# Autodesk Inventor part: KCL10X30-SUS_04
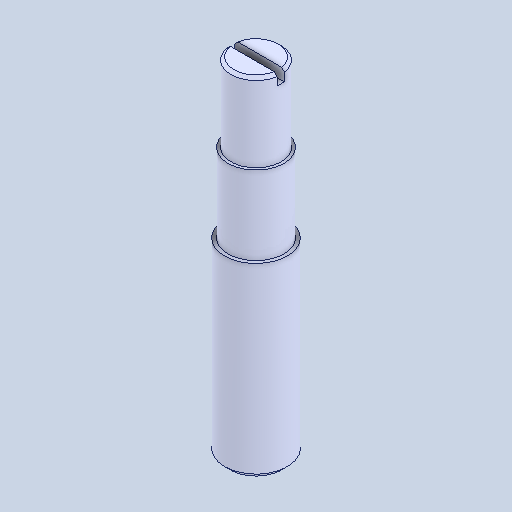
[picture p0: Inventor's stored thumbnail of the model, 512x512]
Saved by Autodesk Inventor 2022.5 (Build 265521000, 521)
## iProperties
Created: 2024-08
Part Number: KCL10X30-SUS_04
Material: 一般
Document SubType Name: Modeling
Designer: ImaoCorp
Density: 1 g/cm^3
Appearance: 既定
Author: ImaoCorp
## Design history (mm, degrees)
feature "KCL10X30-SUS_04"
node "ソリッド1"
